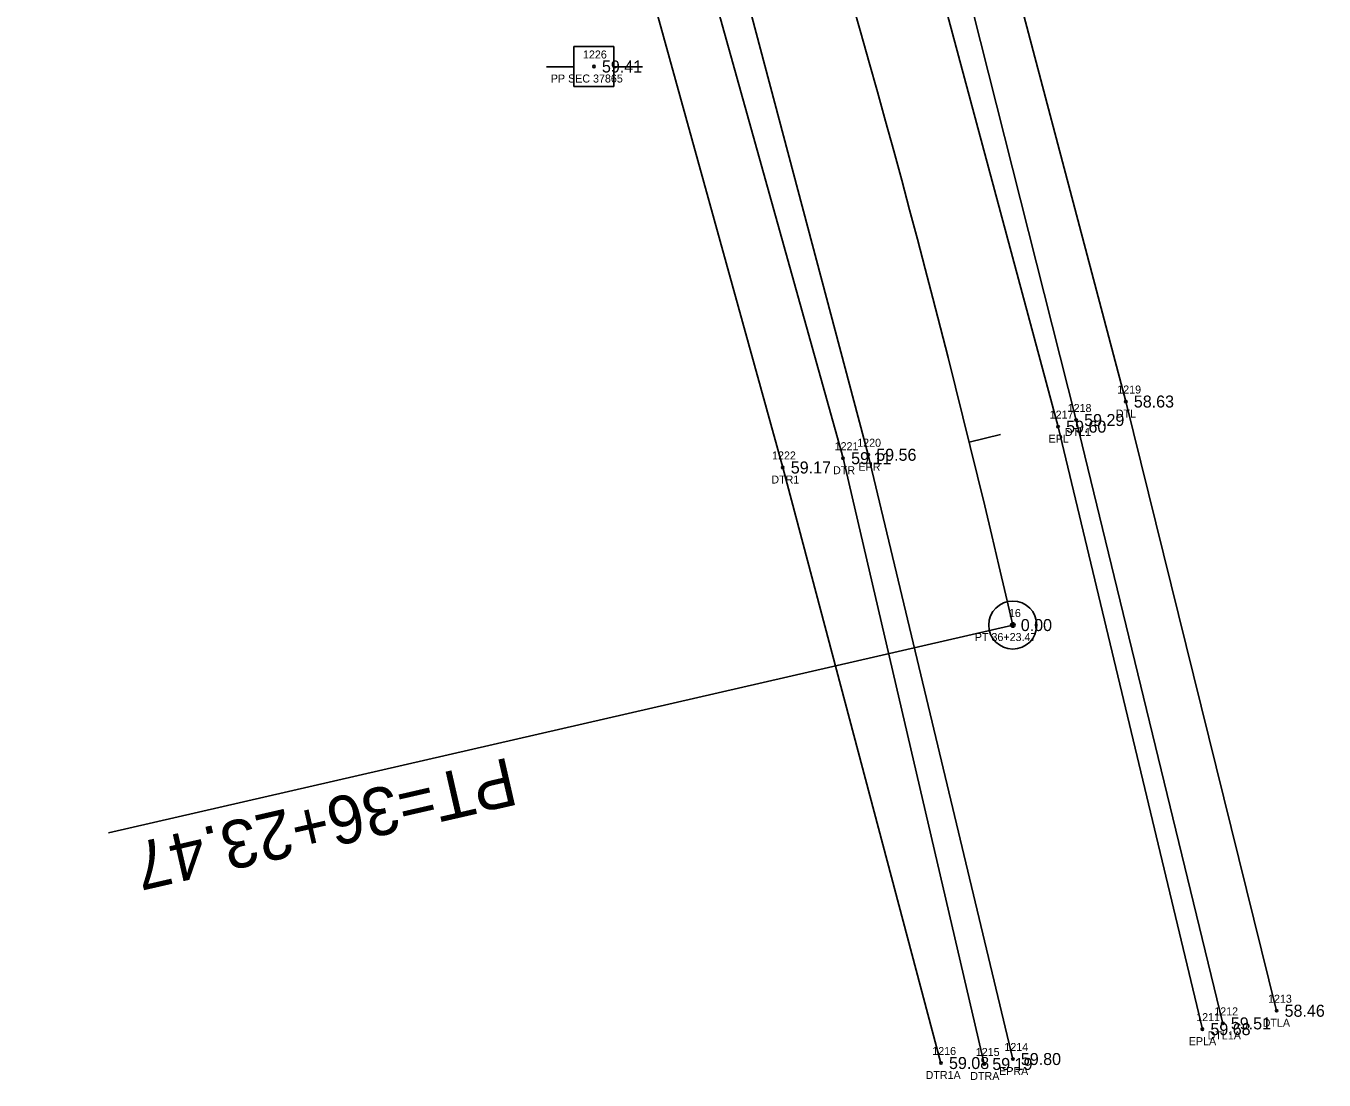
# Model space of a CAD drawing. Extents: x 2396531 to 2397633, y 770203 to 772837.
# Drawn here: x 2397429.9 to 2397592.1, y 770202.9 to 770334.5 of the extents above; entities that cross this region are included whole.
import ezdxf

# ---------------------------------------------------------------- set-up
doc = ezdxf.new("R2010")
doc.units = 0
for name, color, linetype in [('RD_EX_H2O', 7, 'Continuous'), ('RD_EX_H2O_txCode', 7, 'Continuous'), ('RD_EX_Road', 7, 'Continuous'), ('RD_EX_Road_txCode', 7, 'Continuous'), ('RD_EX_TX_H2O_ELEV', 7, 'Continuous'), ('RD_EX_TX_Road_ELEV', 7, 'Continuous'), ('RD_EX_UT', 7, 'Continuous'), ('RD_EX_UT_txCode', 7, 'Continuous'), ('RD_HC_Cl', 7, 'Continuous'), ('RD_HC_Data', 7, 'Continuous'), ('RD_HC_Data_Tic', 7, 'Continuous'), ('RD_HC_Survey_ELEV', 7, 'Continuous'), ('RD_HC_txCode', 7, 'Continuous'), ('RD_SMD_Locator', 7, 'Continuous')]:
    doc.layers.add(name, color=color, linetype=linetype)

msp = doc.modelspace()

# ---------------------------------------------------------------- linework, layer by layer
at = {"layer": 'RD_EX_H2O'}
for points in [[(2397586.15, 770211.51), (2397567.31, 770287.61), (2397548.79, 770357.79), (2397525.19, 770434.22), (2397495.53, 770510.39), (2397465.51, 770576.5), (2397430.55, 770645.5), (2397380.29, 770734.7), (2397327.01, 770824.44), (2397291.42, 770882.36)], [(2397579.43, 770209.93), (2397561.1, 770285.3), (2397543.19, 770356.19), (2397518.98, 770431.67), (2397489.88, 770507.8), (2397460.56, 770573.86), (2397425.02, 770642.83), (2397373.6, 770730.3), (2397319.08, 770819.92), (2397284.14, 770878.8)], [(2397544.21, 770204.98), (2397524.44, 770279.37), (2397505.98, 770346.02), (2397484.83, 770420.44), (2397457.62, 770489.91), (2397433.59, 770544.23), (2397438.3, 770546.59)], [(2397549.62, 770204.86), (2397531.98, 770280.53), (2397513.08, 770348.26), (2397490.2, 770421.93), (2397463.3, 770492), (2397438.3, 770546.59)]]:
    msp.add_lwpolyline(points, dxfattribs=at)
at = {"layer": 'RD_EX_Road'}
for points in [[(2397576.88, 770209.21), (2397558.85, 770284.47), (2397539.93, 770354.87), (2397515.81, 770430.13), (2397486.97, 770506.75), (2397457.82, 770572.7), (2397422.37, 770641.75), (2397371.16, 770729.12), (2397316.57, 770818.52), (2397280.76, 770876.73)], [(2397553.19, 770205.48), (2397535.12, 770280.96), (2397517, 770349.24), (2397493.4, 770422.78), (2397467.13, 770492.9), (2397441.16, 770551.74), (2397436.66, 770561.67), (2397402.21, 770629.28), (2397353, 770712.83), (2397296, 770806.32), (2397260.16, 770864.73)]]:
    msp.add_lwpolyline(points, dxfattribs=at)
at = {"layer": 'RD_EX_UT'}
for p, q in [((2397503.33, 770331.97), (2397498.33, 770331.97)), ((2397498.33, 770331.97), (2397498.33, 770326.97)), ((2397503.33, 770326.97), (2397503.33, 770331.97)), ((2397494.9, 770329.41), (2397498.37, 770329.41)), ((2397503.26, 770329.41), (2397506.9, 770329.41)), ((2397498.33, 770326.97), (2397503.33, 770326.97))]:
    msp.add_line(p, q, dxfattribs=at)
at = {"layer": 'RD_HC_Cl'}
msp.add_arc((2396086.26, 769922.93), 1505.07, 12.92958, 31.50817, dxfattribs=at)
at = {"layer": 'RD_HC_Data'}
msp.add_line((2397553.18, 770259.69), (2397440.16, 770233.74), dxfattribs=at)
for radius in [3, 0.282]:
    msp.add_circle((2397553.18, 770259.69), radius, dxfattribs=at)
at = {"layer": 'RD_HC_Data_Tic'}
msp.add_line((2397547.75, 770282.52), (2397551.63, 770283.48), dxfattribs=at)
at = {"layer": 'RD_SMD_Locator'}
for centre in [(2397500.84, 770329.46), (2397567.31, 770287.61), (2397558.85, 770284.47), (2397561.1, 770285.3), (2397535.12, 770280.96), (2397524.44, 770279.37), (2397531.98, 770280.53), (2397553.18, 770259.69), (2397586.15, 770211.51), (2397576.88, 770209.21), (2397579.43, 770209.93), (2397544.21, 770204.98), (2397549.62, 770204.86), (2397553.19, 770205.48)]:
    msp.add_circle(centre, 0.15, dxfattribs=at)

# ---------------------------------------------------------------- texts
at = {"layer": 'RD_EX_H2O_txCode'}
for s, p in [('1219', (2397566.24, 770288.61)), ('1218', (2397560.04, 770286.3)), ('DTL', (2397566.06, 770285.61)), ('DTL1', (2397559.69, 770283.3)), ('1221', (2397530.92, 770281.53)), ('1222', (2397523.1, 770280.37)), ('DTR', (2397530.72, 770278.53)), ('DTR1', (2397523.01, 770277.37)), ('1213', (2397585.08, 770212.51)), ('1212', (2397578.36, 770210.93)), ('DTLA', (2397584.41, 770209.51)), ('DTL1A', (2397577.53, 770207.93)), ('1216', (2397543.12, 770205.98)), ('1215', (2397548.56, 770205.86)), ('DTR1A', (2397542.29, 770202.98)), ('DTRA', (2397547.87, 770202.86))]:
    msp.add_text(s, height=1, dxfattribs=at).set_placement(p)
at = {"layer": 'RD_EX_Road_txCode'}
for s, p in [('1217', (2397557.79, 770285.47)), ('1220', (2397533.74, 770281.96)), ('EPL', (2397557.65, 770282.47)), ('EPR', (2397533.89, 770278.96)), ('1211', (2397576.1, 770210.21)), ('EPLA', (2397575.18, 770207.21)), ('1214', (2397552.13, 770206.48)), ('EPRA', (2397551.47, 770203.48))]:
    msp.add_text(s, height=1, dxfattribs=at).set_placement(p)
at = {"layer": 'RD_EX_TX_H2O_ELEV'}
for s, p in [('58.63', (2397568.31, 770286.86)), ('59.29', (2397562.1, 770284.55)), ('59.11', (2397532.98, 770279.78)), ('59.17', (2397525.44, 770278.62)), ('58.46', (2397587.15, 770210.76)), ('59.51', (2397580.43, 770209.18)), ('59.08', (2397545.21, 770204.23)), ('59.19', (2397550.62, 770204.11))]:
    msp.add_text(s, height=1.5, dxfattribs=at).set_placement(p)
at = {"layer": 'RD_EX_TX_Road_ELEV'}
for s, p in [('59.60', (2397559.85, 770283.72)), ('59.56', (2397536.12, 770280.21)), ('59.68', (2397577.88, 770208.46)), ('59.80', (2397554.19, 770204.73))]:
    msp.add_text(s, height=1.5, dxfattribs=at).set_placement(p)
at = {"layer": 'RD_EX_UT_txCode'}
for s, p in [('1226', (2397499.47, 770330.46)), ('PP SEC 37865', (2397495.45, 770327.46))]:
    msp.add_text(s, height=1, dxfattribs=at).set_placement(p)
at = {"layer": 'RD_HC_Data'}
msp.add_text('PT=36+23.47', height=6, rotation=192.9296, dxfattribs=at).set_placement((2397490.27, 770243.2))
at = {"layer": 'RD_HC_Survey_ELEV'}
for s, p in [('59.41', (2397501.84, 770328.71)), ('0.00', (2397554.18, 770258.94))]:
    msp.add_text(s, height=1.5, dxfattribs=at).set_placement(p)
at = {"layer": 'RD_HC_txCode'}
for s, p in [('16', (2397552.7, 770260.69)), ('PT 36+23.47', (2397548.44, 770257.69))]:
    msp.add_text(s, height=1, dxfattribs=at).set_placement(p)

doc.saveas('drawing.dxf')
